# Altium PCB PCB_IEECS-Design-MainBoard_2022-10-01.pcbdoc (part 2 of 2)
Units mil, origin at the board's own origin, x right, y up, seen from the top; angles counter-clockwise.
Board outline 4144.93 x 4242 mil, 2 copper layers (Top Layer, Bottom Layer); 143 components, 136 nets, 539 pads, 189 vias.
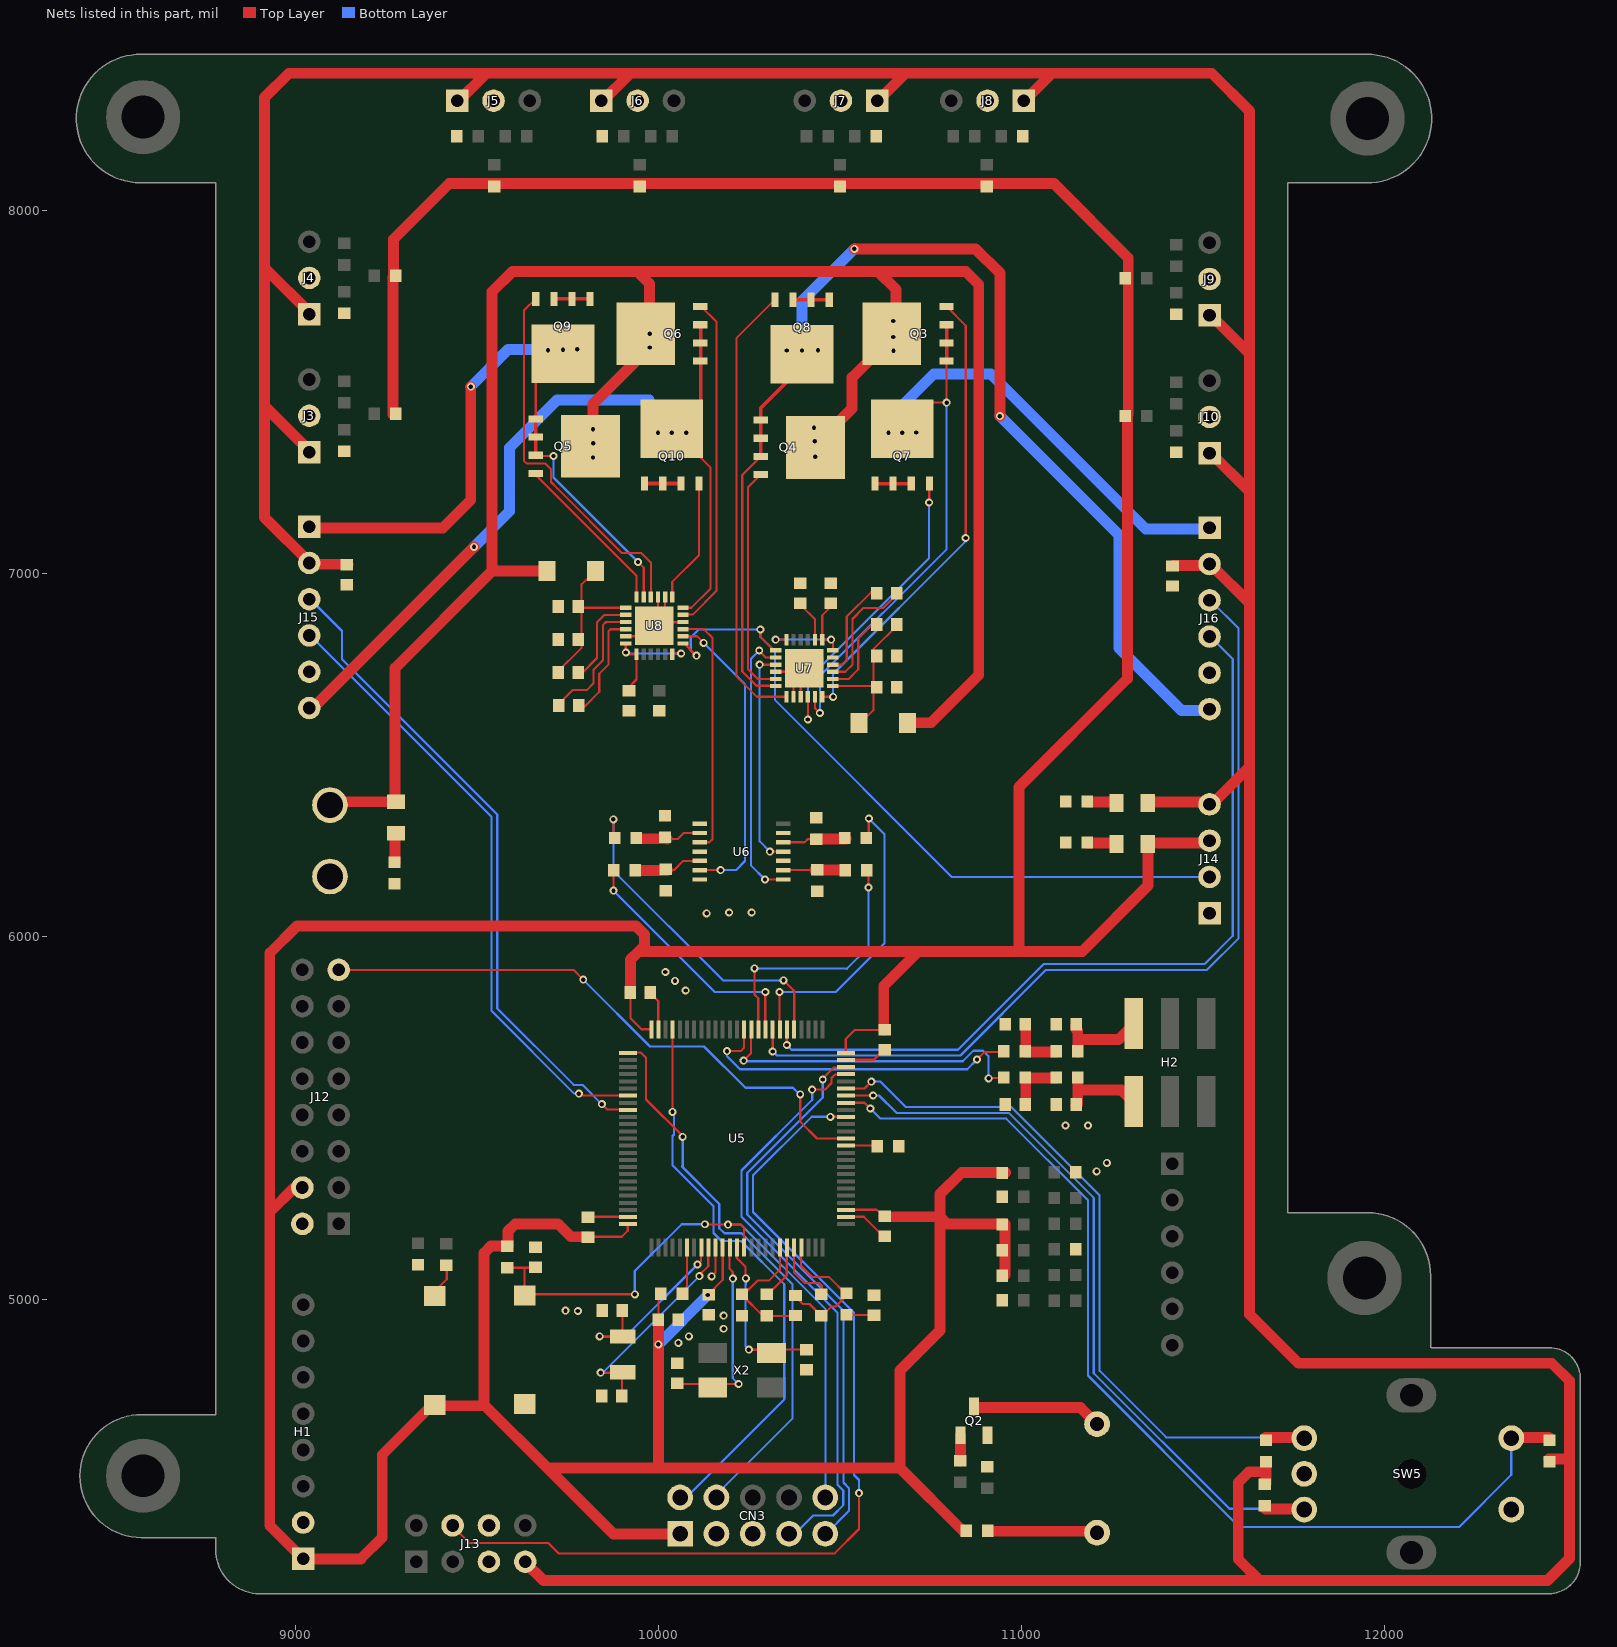
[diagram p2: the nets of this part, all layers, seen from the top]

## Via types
v1: diameter 22, hole 12, Top Layer to Bottom Layer, tented both sides, 157 vias
v2: diameter 23.62, hole 11.81, Top Layer to Bottom Layer, 32 vias

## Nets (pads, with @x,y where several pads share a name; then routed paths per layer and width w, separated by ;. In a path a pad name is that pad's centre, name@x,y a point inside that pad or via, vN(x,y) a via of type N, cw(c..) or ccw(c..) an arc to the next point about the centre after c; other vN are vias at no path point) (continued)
E7: J12.15 U5.38 | length 1639.8
  Top Layer w6: J12.15@9118,5908 9765,5908 v1(9792,5881) v1@9792,5876 ; v1(10390,5565) 10390,5489.42 10436.09,5443.33 U5.38@10516.07,5443.33
  Bottom Layer w6: v1(9792,5881) 9976,5697 10125,5697 10239,5583 10370,5583 10388,5565 v1(10390,5565)
E10: J13.4 U5.41 | length 2600.9
  Top Layer w6: J13.4@9429,4378 9478,4329 9695,4329 9724,4300 10485,4300 10552,4367 v1(10552,4466) ; v1(10473,5503.06) U5.41@10515.33,5503.06
  Bottom Layer w6: v1(10473,5503.06) 10421.25,5503.06 10260,5341.8 10260,5241 10538,4963 10538,4516 10552,4502 v1(10552,4466)
ENCODER_L-A: J15.3 U5.84 | length 1811.4
  Top Layer w6: v1(9843,5537.94) 9857.69,5523.25 9914.16,5523.25 U5.84@9914.67,5522.74
  Bottom Layer w6: J15.3@9043,6925.74 9127,6841.74 9127,6764.37 9555,6336.37 9555,5801.63 9765.63,5591 9789.94,5591 v1(9843,5537.94)
ENCODER_L-B: J15.4 U5.82 | length 1709.7
  Top Layer w6: v1(9780,5567) 9785.56,5561.44 9832.56,5561.44 9833.06,5561.94 9914.91,5561.94 U5.82@9915.41,5561.44
  Bottom Layer w6: J15.4@9043,6825.74 9539,6329.74 9539,5795 9767,5567 v1(9780,5567)
ENCODER_R-A: J16.3 U5.58 | length 2442.7
  Top Layer w6: U5.58@10313.43,5744.33 10313,5743.91 10314,5742.91 v1(10314,5683)
  Bottom Layer w6: v1(10314,5683) 10315,5683 10326,5672 10831.43,5672 11067.43,5908 11511,5908 11598,5995 11598,6848.6 J16.3@11523.86,6922.74
ENCODER_R-B: J16.4 U5.56 | length 2252.9
  Top Layer w6: U5.56@10352.8,5744.33 10353,5744.13 v1(10353,5701)
  Bottom Layer w6: v1(10353,5701) 10366,5688 10824.8,5688 11060.8,5924 11504.37,5924 11582,6001.63 11582,6764.6 J16.4@11523.86,6822.74
GND: C1.1 C2.1 C3.1 C4.1 C17.2 C18.2 C19.2 C20.2 C21.2 C22.1 C23.2 C24.1 C25.1 C26.1 C28.2 C29.2 C30.1 C31.1 C32.1 C33.1 C34.1 C36.1 C40.2 C41.2 C42.2 C43.2 CN3.3 CN3.5 CN4.1 H1.2 J3.2 J4.2 J5.2 J6.2 J7.2 J8.2 J9.2 J10.2 J12.2 J13.5 J13.6 J14.1 J15.5 J16.5 L2.1 Q2.2 Q7.1 Q7.2 Q7.3 Q8.1 Q8.2 Q8.3 Q9.1 Q9.2 Q9.3 Q10.1 Q10.2 Q10.3 R10.1 R11.1 R18.1 R19.1 R20.1 R27.1 R31.1 R32.1 R33.1 R41.1 R42.1 R43.1 R53.1 R54.1 R55.1 R60.2 R61.1 R62.2 R63.1 R66.1 R67.1 R68.1 SW3.2 SW5.C SW5.E U5.10 U5.27 U5.49 U5.74 U5.99 U6.1 U6.4 U6.7 U6.10 U6.13 U7.5 U7.16 U7.20 U7.21 U7.25 U8.5 U8.16 U8.20 U8.21 U8.25 | length 1587.2
  Top Layer w6: C17.2@9808,5227.56 9914.58,5227.56 U5.99@9914.67,5227.47 ; U8.5@9909.32,6827.22 9958.5,6827.22 U8.25@9988,6856.72 ; C21.2@9977.56,5843 9998.47,5822.09 U5.74@9998.47,5744.33 ; U8.21@9997.93,6935.52 U8.25@9997.93,6866.65 ; U8.20@10017.59,6935.52 10017.59,6886.31 U8.25@9997.93,6866.65 ; U8.16@10066.8,6866.62 10066.05,6865.86 U8.25@9997.15,6865.86 ; v1(10146,5063.37) 10156.69,5074.06 U5.10@10156.69,5143 ; U7.16@10322.46,6729.38 10391.36,6729.38 U7.25@10401.26,6739.28 10450.44,6739.28 U7.25@10450.44,6767.99 ; U7.20@10371.67,6660.48 10371.67,6709.69 10391.33,6729.35 U7.21@10391.33,6660.48 ; U5.27@10515.33,5227.47 10564.98,5227.47 C20.2@10620,5172.45 ; U5.49@10515.33,5660.54 10593.09,5660.54 C19.2@10620,5687.45 ; U8.25@9988,6856.72 U8.25@9997.15,6865.86 ; U8.25@9988,6856.72 9988,6865.86 U8.25@9997.15,6865.86 ; U8.25@9997.15,6865.86 U8.25@9997.93,6866.65
  Top Layer w10: Q9.3@9711.01,7757.76 Q9.1@9811.01,7757.76 ; Q10.1@9960.99,7248.24 Q10.3@10060.99,7248.24 ; Q8.3@10370.01,7754.76 Q8.2@10420.01,7754.76 Q8.1@10470.01,7754.76 ; Q7.1@10595.43,7247.24 10645.42,7247.24 Q7.3@10695.43,7247.24
  other v1: 10054,4880 10083,4898 10179,4919 10179,4955 9777,4968 9743,4969 11207,5353 11235,5376 11121,5479 11183,5479 10074,5851 10045,5878 10018,5902 10132,6064 10194,6066 10256,6066
KEY-E: R44.1 SW5.D U5.43 | length 2867.1
  Top Layer w6: U5.43@10516.07,5541.76 10567.24,5541.76 v1(10583,5526)
  Top Layer w30: SW5.D@12349.57,4619.65 R44.1@12453,4619.65
  Bottom Layer w6: v1(10583,5526) 10611,5498 10958,5498 11183,5273 11183,4790 11600.64,4372.36 12205.5,4372.36 12349.57,4516.43 SW5.D@12349.57,4619.65
KEY-L: R45.1 SW5.B U5.44 | length 2124.3
  Top Layer w6: U5.44@10516.07,5561.44 10590.5,5561.44 v1(10591,5561.94)
  Top Layer w30: R45.1@11672,4422.8 SW5.B@11778.7,4422.8
  Bottom Layer w6: v1(10591,5561.94) 10607.06,5561.94 10655,5514 10964.63,5514 11199,5279.63 11199,4796.63 11572.83,4422.8 SW5.B@11778.7,4422.8
KEY-R: R46.1 SW5.A U5.45 | length 2066.2
  Top Layer w6: U5.45@10516.07,5581.13 10567.13,5581.13 v1(10586,5600)
  Top Layer w30: R46.1@11672,4619.65 SW5.A@11778.7,4619.65
  Bottom Layer w6: v1(10586,5600) 10611,5600 10681,5530 10971.25,5530 11215,5286.25 11215,4803.25 11398.61,4619.65 SW5.A@11778.7,4619.65
L_A: J15.1 Q5.1 Q5.2 Q5.3 Q9.5 U8.23 | length 1984.7
  Top Layer w6: Q5.3@9661.12,7326.01 9678,7326.01 9680.01,7324 v1(9710,7324) ; Q5.1@9661.12,7426.01 9661.12,7531.12 Q9.5@9696,7566 ; v1(9943,7032) 9958.58,7016.42 U8.23@9958.58,6935.52
  Top Layer w10: Q5.3@9661.12,7326.01 Q5.2@9661.12,7376.01 Q5.1@9661.12,7426.01
  Top Layer w30: J15.1@9043,7125.74 9404.74,7125.74 9482,7203 v1(9482,7515) ; Q9.5@9696,7566 Q9.5@9736,7606 v1(9736,7617)
  Bottom Layer w6: v1(9710,7324) 9710,7265 v1(9943,7032)
  Bottom Layer w30: v1(9482,7515) 9585,7618 v1(9775,7618) v1@9777,7616
  other v1: 9694.86,7616
L_B: J15.6 Q6.1 Q6.2 Q6.3 Q10.5 U8.18 | length 2290.1
  Top Layer w6: Q10.5@10036,7399.12 10143,7292.12 10143,6959.19 10089.78,6905.97 U8.18@10066.8,6905.97
  Top Layer w10: Q10.5@10036,7399.12 10115.76,7478.88 Q6.3@10115.76,7686.99
  Top Layer w30: J15.6@9043,6625.74 v1(9491,7073.74)
  Bottom Layer w30: v1(9491,7073.74) 9589,7171.74 9589,7347 9720,7478 9974,7478
  other v1: 9998,7388.12 10036,7388.12 10076,7388.12
L_EN: U6.6 U8.14 | length 848.4
  Top Layer w6: U8.14@10066.8,6827.27 10105.73,6827.27 v1(10124,6809) ; U6.6@10113,6182.82 v1(10170.82,6182.82)
  Bottom Layer w6: v1(10124,6809) 10237.96,6695.04 10237.96,6207.96 10212.82,6182.82 v1(10170.82,6182.82)
L_EN_PWM: R58.1 U5.59 | length 692.3
  Top Layer w6: v1@9875,6126 v1(9875.25,6126.25) 9875.51,6126.51 R58.1@9875.51,6181.32 ; U5.59@10293.74,5744.33 v1(10293.74,5846.89)
  Bottom Layer w6: v1(9875.25,6126.25) 10154.62,5846.89 v1(10293.74,5846.89)
L_PH: U6.3 U8.15 | length 684.5
  Top Layer w6: U8.15@10066.8,6846.96 10123.95,6846.96 10148,6822.91 10148,6268 10139.59,6259.59 U6.3@10113.08,6259.59
L_PH_DIR: R56.1 U5.55 | length 937.4
  Top Layer w6: v1(9875,6323) 9875.51,6322.49 R56.1@9875.51,6269.32 ; v1(10344,5879) 10373.22,5849.78 U5.55@10373.22,5743.67
  Bottom Layer w6: v1(9875,6323) 9875,6181 10177,5879 v1(10344,5879)
NetBUZZER1_1: BUZZER1.1 R7.2 | length 297.5
  Top Layer w30: R7.2@10906.51,4361 BUZZER1.1@11204,4361
NetBUZZER1_2: BUZZER1.2 Q2.3 | length 351.6
  Top Layer w30: Q2.3@10869.91,4702.43 11161.78,4702.43 BUZZER1.2@11204,4660.21
NetC1_2: C1.2 R1.2 R2.1 | length 160.7
  Top Layer w30: C1.2@11011.56,5534 11011.56,5609.3 11010.85,5610 R2.1@11095.29,5610
NetC3_2: C3.2 R3.1 R4.2 | length 157.7
  Top Layer w30: C3.2@11011.56,5755 11011.56,5682.7 11010.85,5682 R3.1@11095.29,5682
NetC28_1: C28.1 L3.1 | length 77
  Top Layer w6: L3.1@10519,4956.89 C28.1@10596,4956.89
NetC32_2: C32.2 C34.2 C35.1 D5.2 U7.1 | length 428.9
  Top Layer w6: U7.1@10479.92,6690.02 C32.2@10591.56,6690.02 ; D5.2@10557.14,6589.03 10591.57,6623.45 10591.57,6690.03 10591.57,6776.36 10591.57,6791.83 C35.1@10662.43,6862.7
NetC33_2: C33.2 C36.2 C37.1 D6.2 U8.1 | length 448.7
  Top Layer w6: C37.1@9716.57,6724.66 9787.43,6795.52 9787.43,6815.31 C36.2@9787.43,6905.97 ; D6.2@9823.93,7006.97 9787.43,6970.47 C36.2@9787.43,6905.97 ; U8.1@9909.34,6905.98 C36.2@9787.43,6905.97
NetC35_2: C35.2 U7.2 | length 224.7
  Top Layer w6: U7.2@10479.94,6709.69 10523.32,6709.69 10550,6736.37 10550,6821.13 C35.2@10591.57,6862.7
NetC37_2: C37.2 U8.2 | length 246.7
  Top Layer w6: C37.2@9787.43,6724.66 9830,6767.22 9830,6866 9850.31,6886.31 U8.2@9909.32,6886.31
NetC38_1: C38.1 U7.3 | length 347.3
  Top Layer w6: U7.3@10479.94,6729.37 10514.37,6729.37 10534,6749 10534,6875 10564,6905 10618.4,6905 C38.1@10662.43,6949.03
NetC38_2: C38.2 U7.4 | length 265.1
  Top Layer w6: U7.4@10479.94,6749.09 10506.09,6749.09 10518,6761 10518,6881.63 10585.4,6949.03 C38.2@10591.57,6949.03
NetC39_1: C39.1 U8.3 | length 366.9
  Top Layer w6: C39.1@9717.57,6634 9762.57,6679 9801.5,6679 9820.12,6697.62 9820.12,6734.71 9846,6760.59 9846,6858 9854.63,6866.63 U8.3@9909.32,6866.63
NetC39_2: C39.2 U8.4 | length 292.3
  Top Layer w6: C39.2@9788.43,6634 9796,6634 9836.12,6674.12 9836.12,6724.12 9862,6750 9862,6842 9866.91,6846.91 U8.4@9909.32,6846.91
NetC40_1: C40.1 U7.6 U7.7 U7.12 | length 343.7
  Top Layer w6: v1(10322,6818) U7.12@10351.96,6818 ; C40.1@10477,6911.57 10450.4,6884.97 U7.7@10450.4,6818 v1(10475,6818) 10479.94,6813.06 U7.6@10479.94,6788.48
  Bottom Layer w6: v1(10322,6818) v1(10475,6818)
NetC41_1: C41.1 U8.6 U8.7 U8.12 | length 339.1
  Top Layer w6: U8.6@9909.32,6807.52 v1(9909.32,6782.68) 9914,6778 U8.7@9938.86,6778 9938.86,6708.29 C41.1@9915,6684.43 ; U8.12@10037.3,6778 10039.3,6780 v1(10062,6780)
  Bottom Layer w6: v1(9909.32,6782.68) 9912,6780 v1(10062,6780)
NetC42_1: C42.1 U7.8 | length 109.2
  Top Layer w6: C42.1@10393,6911.57 10430.71,6873.86 U7.8@10430.71,6818
NetLED3_1: LED3.1 R66.2 | length 80.2
  Top Layer w30: R66.2@11181.37,6257.59 LED3.1@11261.55,6257.59
NetLED4_1: LED4.1 R67.2 | length 80.2
  Top Layer w30: R67.2@11181.37,6370.59 LED4.1@11261.55,6370.59
NetLED5_1: LED5.1 R68.2 | length 80.2
  Top Layer w30: R68.2@9273.41,6204.37 LED5.1@9273.41,6284.55
NetQ2_1: Q2.1 R9.2 | length 70.9
  Top Layer w30: R9.2@10830.92,4555.07 10831.51,4555.66 Q2.1@10831.51,4625.7
NetQ3_4: Q3.4 U7.24 | length 1278.8
  Top Layer w6: U7.24@10450.37,6660.48 v1(10480.48,6660.48) ; Q3.4@10793.32,7735.99 10846,7683.31 v1(10846,7098)
  Bottom Layer w6: v1(10480.48,6660.48) 10480.48,6723.48 10846,7089 v1(10846,7098)
NetQ4_4: Q4.4 U7.17 | length 638.5
  Top Layer w6: Q4.4@10281.24,7273.01 10246,7237.77 10246,6736.69 10272.95,6709.74 U7.17@10322.46,6709.74
NetQ5_4: Q5.4 U8.24 | length 455.5
  Top Layer w6: Q5.4@9661.12,7276.01 9661.12,7271.61 9713.34,7219.38 9938.89,6993.84 U8.24@9938.89,6935.52
NetQ6_4: Q6.4 U8.17 | length 922
  Top Layer w6: U8.17@10066.8,6886.26 10067.6,6887.06 10093.5,6887.06 10159,6952.56 10159,7693.76 Q6.4@10115.76,7736.99
NetQ7_4: Q7.4 U7.22 | length 850.2
  Top Layer w6: v1(10410.97,6598.03) U7.22@10410.97,6660.48 ; v1(10745,7196) 10745.43,7196.43 Q7.4@10745.43,7247.24
  Bottom Layer w6: v1(10410.97,6598.03) 10410.97,6707.97 10745,7042 v1(10745,7196)
NetQ8_4: Q8.4 U7.19 | length 1243.1
  Top Layer w6: Q8.4@10320.01,7754.76 10214,7648.76 10214,6717 10270.52,6660.48 U7.19@10351.98,6660.48
NetQ9_4: Q9.4 U8.22 | length 1042.4
  Top Layer w6: Q9.4@9661.01,7757.76 9628.43,7725.19 9628.43,7310.78 9636.05,7303.16 9687.84,7303.16 9702.98,7288.02 9702.98,7252.37 9719.97,7235.38 9898.35,7057 9951.94,7057 9978.29,7030.65 U8.22@9978.29,6935.52
NetQ10_4: Q10.4 U8.19 | length 343.2
  Top Layer w6: U8.19@10037.28,6935.52 10037.28,6977.28 10110.99,7050.99 Q10.4@10110.99,7248.24
NetR27_2: R27.2 U5.37 | length 94.8
  Top Layer w6: U5.37@10515.33,5424.32 10515.65,5424 R27.2@10610,5424
NetR34_1: R34.1 SW4.1 | length 98.2
  Top Layer w6: SW4.1@9373,5006 9373,5012 9416,5055 R34.1@9416,5086.35
NetR56_2: R56.2 R60.1 U6.2 | length 181.6
  Top Layer w6: R60.1@10023,6268.81 10052.26,6268.81 10068.63,6285.18 U6.2@10113.08,6285.18
  Top Layer w30: R56.2@9938.5,6269.32 10022.48,6269.32 R60.1@10023,6268.81
NetR57_1: R57.1 R61.2 U6.12 | length 176.6
  Top Layer w6: U6.12@10343.39,6259.59 10402,6259.59 10411.24,6268.83 R61.2@10430,6268.83
  Top Layer w30: R61.2@10430,6268.83 10515.51,6268.83 R57.1@10516,6269.32
NetR58_2: R58.2 R62.1 U6.5 | length 185.8
  Top Layer w6: R62.1@10024,6182.84 10041.84,6182.84 10067.41,6208.41 U6.5@10113.08,6208.41
  Top Layer w30: R58.2@9938.5,6181.32 10022.48,6181.32 R62.1@10024,6182.84
NetR59_1: R59.1 R63.2 U6.9 | length 172.2
  Top Layer w6: U6.9@10343.39,6182.82 R63.2@10431,6182.82
  Top Layer w30: R63.2@10431,6182.82 10513.52,6182.82 R59.1@10515.01,6181.32
NSLEEP: J14.2 U7.13 U8.13 | length 2004.7
  Top Layer w6: U8.13@10066.8,6807.56 10070.44,6807.56 v1(10104,6774) ; v1(10280,6846) 10280,6826.03 10317.59,6788.44 U7.13@10322.46,6788.44
  Bottom Layer w6: v1(10104,6774) 10102,6774 10088,6788 10088,6824 10110,6846 v1(10280,6846) 10280,6826.06 10320,6786.06 10320,6652 10808.41,6163.59 J14.2@11523.86,6163.59
OSC32IN: C22.2 U5.8 X1.2 | length 527.7
  Top Layer w6: v1@9844.89,4896.43 9899,4896.43 9900,4897.43 C22.2@9900,4966 ; v1(10107,5096) 10116.58,5105.58 U5.8@10116.58,5143.67
  Bottom Layer w6: v1(9837,4898) 9909,4898 v1(10107,5096)
OSC32OUT: C24.2 U5.9 X1.1 | length 600.6
  Top Layer w6: v1(9840,4798) 9899,4798 9899,4731.56 C24.2@9899.56,4731 ; v1(10112,5064) 10112,5067.06 10136.26,5091.32 U5.9@10136.26,5143.67
  Bottom Layer w6: v1(9840,4798) 9843,4795 v1(10112,5064)
OSC_IN: C25.2 U5.12 X2.1 | length 559.9
  Top Layer w6: C25.2@10048,4767.89 10049.13,4766.76 10151.29,4766.76 v1(10220.24,4766.76) ; U5.12@10195.32,5143.67 10195.32,5084.2 10204,5075.52 v1(10204,5057)
  Bottom Layer w6: v1(10204,5057) 10204,4783 v1(10220.24,4766.76)
OSC_OUT: C26.2 U5.13 X2.3 | length 458.9
  Top Layer w6: U5.13@10215,5143.67 10215,5114 10239,5090 10239,5059 v1(10240,5058) ; v1(10248.24,4861.24) 10312.71,4861.24 10313.02,4861.56 C26.2@10410,4861.56
  Bottom Layer w6: v1(10240,5058) 10240,5041 10239,5040 10239,4870.49 v1(10248.24,4861.24)
PB10: CN3.7 U5.47 | length 1641.9
  Top Layer w6: v1(10423,5578) 10457.94,5578 10476,5596.06 10476,5609.97 10486.02,5619.99 10514.16,5619.99 U5.47@10515.33,5621.17
  Bottom Layer w6: CN3.7@10360,4353 10374,4353 10425.57,4404.57 10480.06,4404.57 10508.43,4432.94 10508.43,4473.06 10493,4488.49 10493,4962.37 10228,5227.37 10228,5355.06 10423,5550.06 v1(10423,5578)
PB11: CN3.9 U5.48 | length 1561.8
  Top Layer w6: v1(10452,5606) 10452,5608.6 10482.41,5639.01 10514.9,5639.01 U5.48@10516.07,5640.18
  Bottom Layer w6: v1(10452,5606) 10452,5556.43 10244,5348.43 10244,5234 10509,4969 10509,4495.12 10524.43,4479.69 10524.43,4417.43 CN3.9@10460,4353
PWM_DAC_0: R4.1 U5.62 | length 914.3
  Top Layer w6: v1(10188,5684) 10226,5684 10234.69,5692.69 U5.62@10234.69,5744.33 ; v1(10877,5661) 10898,5682 R4.1@10951.54,5682
  Bottom Layer w6: v1(10188,5684) 10188,5670 10224,5634 10850,5634 v1(10877,5661)
PWM_DAC_0-OUT: C4.2 H2.6 R3.2 | length 246.4
  Top Layer w30: C4.2@11150.31,5755 11150.31,5744.69 11154.6,5740.4 11154.6,5716 ; R3.2@11154.6,5682 11154.6,5716 ; H2.6@11309,5757.48 11267.52,5716 11154.6,5716
PWM_DAC_1: R1.1 U5.61 | length 892.8
  Top Layer w6: v1(10234,5658) 10254.37,5678.37 U5.61@10254.37,5744.33 ; v1(10909,5609) 10910,5610 R1.1@10951.54,5610
  Bottom Layer w6: v1(10234,5658) 10236,5656 10838.06,5656 10867.06,5685 10894,5685 10909,5670 v1(10909,5609)
PWM_DAC_1-OUT: C2.2 H2.5 R2.2 | length 246.5
  Top Layer w30: C2.2@11150.31,5534 11154.6,5538.29 11154.6,5577 ; R2.2@11154.6,5610 11154.6,5577 ; H2.5@11309,5542.52 11274.52,5577 11154.6,5577
Q3_4: 
Q4_4: 
Q7_4: 
Q8_4: 
R_A: J16.1 Q3.1 Q3.2 Q3.3 Q7.5 U7.23 | length 2611.1
  Top Layer w6: U7.23@10430.68,6660.48 10430.68,6629.32 v1(10444,6616) ; v1(10671,7388) 10671,7393.1 10726.36,7448.45 10703.49,7471.32 v1(10793.32,7471.32) Q3.1@10793.32,7585.99
  Top Layer w10: Q3.1@10793.32,7585.99 Q3.2@10793.32,7635.99 Q3.3@10793.32,7685.99
  Bottom Layer w6: v1(10444,6616) 10444,6718 10793.32,7067.32 v1(10793.32,7471.32)
  Bottom Layer w30: v1(10671,7388) 10671,7463 10758,7550 10915,7550 11342.26,7122.74 J16.1@11523.86,7122.74
  other v1: 10633,7388.12 10710,7389
R_B: J16.6 Q4.1 Q4.2 Q4.3 Q8.5 U7.18 | length 3326.8
  Top Layer w6: Q4.3@10281.24,7323.01 10230,7271.77 10230,6730.06 10269.23,6690.84 10321.66,6690.84 U7.18@10322.46,6690.03
  Top Layer w10: Q4.3@10281.24,7323.01 Q4.2@10281.24,7373.01 Q4.1@10281.24,7423.01 10281.24,7456.24 10395,7570 v1(10395,7615)
  Top Layer w30: v1(10539,7895) 10873,7895 10940,7828 v1(10940,7434)
  Bottom Layer w30: v1(10395,7615) 10395,7751 v1(10539,7895) ; v1(10940,7434) 11268,7106 11268,6795 11440.26,6622.74 J16.6@11523.86,6622.74
  other v1: 10353,7615 10439,7616
R_EN: U6.8 U7.14 | length 755.8
  Top Layer w6: v1@10280,6784 10295.27,6768.73 U7.14@10322.46,6768.73 ; v1(10292.77,6157.23) U6.8@10343.39,6157.23
  Bottom Layer w6: v1(10277,6788) 10253.96,6764.96 10253.96,6196.04 v1(10292.77,6157.23)
R_EN_PWM: R59.2 U5.60 | length 721.4
  Top Layer w6: v1(10264,5912) 10264,5840 10274.06,5829.94 U5.60@10274.06,5744.33 ; v1(10578,6135) R59.2@10578,6181.32
  Bottom Layer w6: v1(10264,5912) 10517,5912 10518,5911 10578,5971 v1(10578,6135)
R_PH: U6.11 U7.15 | length 609.6
  Top Layer w6: v1(10277.96,6749.04) U7.15@10322.46,6749.04 U7.15@10321.7,6748.28 ; v1(10306,6234) U6.11@10343.39,6234
  Bottom Layer w6: v1(10277.96,6749.04) 10277.96,6262.04 v1(10306,6234)
R_PH_DIR: R57.2 U5.57 | length 864.7
  Top Layer w6: v1(10333,5847) 10333.11,5846.89 U5.57@10333.11,5744.33 ; R57.2@10578.99,6269.32 v1(10578.99,6324.99)
  Bottom Layer w6: v1(10333,5847) 10488,5847 10622,5981 10622,6281.98 v1(10578.99,6324.99)
RST: C29.1 CN3.10 R21.1 SW3.1 U5.14 | length 1827.9
  Top Layer w6: R21.1@9585,5087.35 9630,5087.35 ; C29.1@9663,5089 9661.35,5087.35 9630,5087.35 ; v1(9934,5014) 9640.39,5014 9638.39,5016 9630,5007.61 9630,5087.35 ; v1(10127,5207) 10128,5206 v1(10191,5206) 10226,5206 10234.69,5197.31 U5.14@10234.69,5143.67
  Bottom Layer w6: v1(9934,5014) 9934,5078 10063,5207 v1(10127,5207) ; v1(10191,5206) 10226.75,5206 10460,4972.75 CN3.10@10460,4453
SWCLK: CN3.4 U5.76 | length 1552.4
  Top Layer w6: U5.76@9914.67,5680.22 9950.78,5680.22 9965,5666 9965,5551 10066,5450 v1(10066,5448)
  Bottom Layer w6: v1(10066,5448) 10066,5368 10064,5366 10167,5263 10167,5196.06 10181.06,5182 10228.12,5182 10369,5041.12 10369,4672 10160,4463 CN3.4@10160,4453
SWDIO: CN3.2 U5.72 | length 1580.9
  Top Layer w6: v1(10037.84,5516.84) U5.72@10037.84,5744.33
  Bottom Layer w6: v1(10037.84,5516.84) 10041.89,5512.78 10041.89,5454.43 10037.84,5450.37 10037.84,5369.54 10151,5256.37 10151,5183 10173,5161 10226.49,5161 10346,5041.49 10346,4724 10075,4453 CN3.2@10060,4453
U8_17: 
U8_19: 
U8_22: 
U8_24: 
VBAT: R8.2 U5.6 | length 137.4
  Top Layer w6: R8.2@10057.66,5014 10077.95,5034.29 U5.6@10077.95,5143
VCC: CN4.2 D5.1 D6.1 LED5.2 Q3.5 Q4.5 Q5.5 Q6.5 | length 5704.6
  Top Layer w30: CN4.2@9082,6374.74 9085.58,6371.16 9273.41,6371.16 9273.41,6739.41 9540.97,7006.97 ; D6.1@9690.07,7006.97 9540.97,7006.97 ; Q5.5@9765,7335 Q5.5@9765,7345 ; Q5.5@9800.88,7351 9819,7369.12 v1(9819,7398) 9819,7467 v1(9975,7623) ; v1(9975,7661) 9975,7799 9941,7833 ; Q4.5@10421,7348 10426,7348 10533,7455 10533,7541 10533.55,7541 Q3.5@10653.55,7661 10653.55,7783.45 10604,7833 ; D5.1@10691,6589.03 10750.03,6589.03 10882,6721 10882,7797 10846,7833 10604,7833 ; 9540.97,7006.97 9540.97,7776.62 9597.35,7833 9941,7833 ; 9941,7833 10604,7833
  other v1: 9819,7320 10431,7322 9819.67,7359 10430,7365 10428,7402 10647,7614 10646,7652 10646,7696
VCC3V3: C17.1 C18.1 C19.1 C20.1 C21.1 C23.1 CN3.1 H1.1 J12.4 J14.3 LED3.2 R7.1 R8.1 R12.2 R13.2 R14.2 R21.2 R24.2 R25.2 R26.2 R35.2 R36.2 R37.2 R47.2 R48.2 R49.2 SW4.2 U5.11 U5.28 U5.50 U5.75 U5.100 | length 16114.7
  Top Layer w6: C17.1@9808,5172.45 9898.45,5172.45 9914.67,5188.67 U5.100@9914.67,5207.78 ; C21.1@9922.45,5843 9922.45,5774.55 9952.67,5744.33 U5.75@9978.78,5744.33 ; R8.1@9999.69,5019 9999.69,4946.31 C18.1@10000,4946 ; v1(10135,5012) 10176.63,5053.63 U5.11@10176.63,5117.67 ; U5.28@10515.33,5247.15 10600.41,5247.15 C20.1@10620,5227.56 ; U5.50@10515.33,5680.22 10515.33,5717.33 10540.56,5742.56 C19.1@10620,5742.56
  Top Layer w30: J12.4@9018,5308 8996,5308 8928,5240 ; R12.2@9267.31,7439 9267.31,7817 9269.31,7819 9269.31,7921.31 9422.69,8074.69 9545,8074.69 9946,8074.69 11089.31,8074.69 11293.89,7870.11 11293.89,7816 11293.89,7438.55 11291.35,7436 11291.35,6710.35 10993,6412 10993,5959 ; 9519,4707 9519,5128 9537.66,5146.66 9585,5146.66 9585,5188.65 9604.46,5208.11 9722.89,5208.11 9758.55,5172.45 C17.1@9808,5172.45 ; C21.1@9922.45,5843 9922.45,5936.45 9945,5959 ; C18.1@9999.44,4941 9999.44,4539.56 10004,4535 ; CN3.1@10060,4353 9875,4353 9693,4535 ; C20.1@10620,5227.56 10775.44,5227.56 ; C19.1@10620,5742.56 10620,5864 10715,5959 ; R7.1@10839.35,4361 10665.35,4535 ; R49.2@10954.69,5066.7 10954.69,5137.41 10954.69,5208.11 10794.89,5208.11 10775.44,5227.56 ; R37.2@10955.35,5350 10835,5350 10775.44,5290.44 10775.44,5227.56 ; J14.3@11523.86,6263.59 11517.86,6257.59 11348.16,6257.59 11348.16,6140.16 11167,5959 10993,5959 ; 8928,5240 8928,5954 9003,6029 9937,6029 9960.5,6005.5 9960.5,5974.5 9945,5959 ; 8928,5240 8928,4377 H1.1@9020,4285 9179,4285 9238,4344 9238,4571.79 9373,4706.79 9521.21,4706.79 9693,4535 ; 9693,4535 10004,4535 ; 9945,5959 10715,5959 ; 10004,4535 10665.35,4535 ; 10665.35,4535 10665.35,4804.35 10775.44,4914.44 10775.44,5227.56 ; 10715,5959 10993,5959
  Bottom Layer w30: v1(9999,4876) v1(10135,5012)
VCC5V: C30.2 C31.2 J3.1 J4.1 J5.1 J6.1 J7.1 J8.1 J9.1 J10.1 J13.7 J14.4 J15.2 J16.2 LED4.2 R44.2 R45.2 R46.2 | length 14096.3
  Top Layer w30: J3.1@9039,7337 8914,7462 ; J4.1@9040,7717 8914,7843 ; C30.2@9143.16,7025.56 9142.98,7025.74 9043,7025.74 8914,7154.74 8914,7462 ; J5.1@9443,8297 9525,8379 ; J13.7@9629,4278 9682,4225 11656,4225 ; J6.1@9844,8301 9922,8379 ; J7.1@10600,8299 10680,8379 ; J8.1@11003.89,8299 11083.89,8379 ; LED4.2@11348.16,6370.59 11516.86,6370.59 11523.86,6363.59 11628,6467.74 ; C31.2@11418.7,7021.94 11523.06,7021.94 11523.86,7022.74 11628,6918.6 ; J10.1@11519.86,7334 11628,7225.86 ; J9.1@11519.86,7714 11628,7605.86 ; R45.2@11670.41,4489.96 11673.59,4493.15 R46.2@11673.59,4552.48 ; 11672,4525 11627,4525 11597,4495 11597,4284 11656,4225 ; R44.2@12453,4560.34 12495.34,4560.34 ; 8914,7462 8914,7843 ; 8914,7843 8914,8312 8981,8379 9525,8379 ; 9525,8379 9922,8379 ; 9922,8379 10680,8379 ; 10680,8379 11083.89,8379 ; 11083.89,8379 11524,8379 11628,8275 11628,7605.86 ; 11628,6467.74 11628,4959 11763,4824 12461,4824 12509.41,4775.59 12509.41,4771.04 12510,4770.45 12510,4285.96 12449.04,4225 11656,4225 ; 11628,6467.74 11628,6918.6 ; 11628,6918.6 11628,7225.86 ; 11628,7225.86 11628,7605.86
VDDA: C27.1 L3.2 R23.1 U5.22 | length 402.2
  Top Layer w6: C27.1@10375,5009 10397,4987 10415.69,4987 10449,4953.69 10475.31,4980 10487,4980 10519,5012 10469.65,5061.35 10423.65,5061.35 10392.17,5092.83 U5.22@10392.17,5143.67
VREF+: R23.2 U5.21 | length 185.4
  Top Layer w6: U5.21@10372.48,5143.67 10372.48,5075.52 10402.65,5045.35 10442,5045.35 10449,5038.35 R23.2@10449,5013
VREF-: R22.2 U5.20 | length 153.9
  Top Layer w6: R22.2@10299,5012 10352.8,5065.8 U5.20@10352.8,5143.67
VSSA: C27.2 L2.2 R22.1 U5.19 | length 361.7
  Top Layer w6: U5.19@10333.11,5143 U5.19@10333.11,5143.67 ; U5.19@10333.85,5143 10333.85,5081.85 10303.56,5051.56 10272,5051.56 10231,5010.56 10287.66,4953.89 C27.2@10375,4953.89
pads on no net: CN3.6 CN3.8 H1.7 H1.8 J13.2 J13.8 SP6.1 SP7.1 SP8.1 SP9.1 SW5. SW5.6 SW5.7 U5.35 U5.36 U5.39 U5.40 U5.42 U5.46 U5.51 U5.53 U5.63 U5.64 U5.65 U5.66 U5.67 U5.68 U5.69 U5.70 U5.71 U5.73 U5.77 U5.79 U5.80 U5.83 U5.92 U5.95 U5.96 U7.9 U7.10 U7.11 U8.9 U8.10 U8.11 X2.2 X2.4
copper on no net:
  other v2: 8579,4427.39 8517.75,4452.75 8640.25,4452.75 8492.39,4514 8665.61,4514 8517.75,4575.25 8640.25,4575.25 8579,4600.61 11945,4972.39 11883.75,4997.75 12006.25,4997.75 11858.39,5059 12031.61,5059 11883.75,5120.25 12006.25,5120.25 11945,5145.61 11953.18,8167.39 8579,8171.39 11891.93,8192.75 12014.42,8192.75 8517.75,8196.75 8640.25,8196.75 11866.56,8254 12039.79,8254 8492.39,8258 8665.61,8258 11891.93,8315.25 12014.42,8315.25 8517.75,8319.25 8640.25,8319.25 11953.18,8340.61 8579,8344.61

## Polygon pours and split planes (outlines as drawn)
GND on Top Layer (solid, remove dead copper, pour order 0): 8313,8625 12637.1,8625 12637.1,5051 12637.1,4062 12646.1,4053 12628.1,4035 8295.11,4035
GND on Bottom Layer (solid, remove dead copper, pour order 2): 8239,8613 8624.01,8619.32 12670.01,8619.32 12670.01,5045.32 12670.01,4056.32 12679.01,4047.32 12661.01,4029.32 8239,4029.32

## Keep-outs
Keep-Out Layer:
  the board outline again, w10

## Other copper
Top Layer:
  region net R_B: 10482.41,7682.86 10309.18,7682.86 10309.18,7521.44 10482.41,7521.44
  region net VCC: 10354.15,7431.41 10354.15,7258.18 10515.56,7258.18 10515.56,7431.41
  region net R_A: 10757.41,7480.86 10584.18,7480.86 10584.18,7319.44 10757.41,7319.44
  region net VCC: 10559.15,7748.41 10559.15,7575.18 10720.56,7575.18 10720.56,7748.41
Bottom Layer:
  rectangle net VCC: 9733,7267 9895,7440
  rectangle net L_B: 9946,7318 10126,7482
  rectangle net VCC: 9880,7573 10047,7750
  rectangle net L_A: 9646,7524 9826,7689
  region net R_B: 10482.61,7685.52 10308.5,7685.52 10308.5,7521 10482.61,7521
  region net VCC: 10348.48,7437.61 10348.48,7257 10516,7257 10516,7437.61
  region net R_A: 10757.61,7481 10583.5,7481 10583.5,7317 10757.61,7317
  region net VCC: 10559,7749.61 10559,7573 10723,7573 10723,7749.61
